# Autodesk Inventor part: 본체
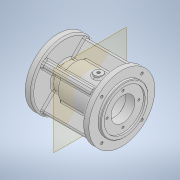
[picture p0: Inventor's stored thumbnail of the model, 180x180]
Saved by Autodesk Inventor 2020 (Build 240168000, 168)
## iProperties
Created: 2024-10
Part Number: 본체
Material: 일반
Document SubType Name: Modeling
Designer: oem
Density: 1 g/cm^3
Appearance: 기본값
Author: oem
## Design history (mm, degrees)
sketch "스케치1"
  geometry: L1 (-61, 0)-(61, 0); L2 (-61, 42)-(-56, 42); L3 (-56, 42)-(-56, 58); L4 (-56, 58)-(-44, 58); L5 (-44, 58)-(-44, 23); L6 (44, 58)-(56, 58); L7 (56, 58)-(56, 42); L8 (56, 42)-(61, 42); L9 (61, 42)-(61, 0); L10 (-61, 42)-(-61, 0); L11 (44, 58)-(44, 30); L12 (-44, 23)-(-29, 23); L13 (-29, 23)-(-29, 30); L14 (-29, 30)-(44, 30); 2 further points
  constraints: 28 end point, 7 perpendicular, 3 horizontal, 2 vertical, 1 coincident, 1 midpoint
  dimensions: "d0" = 122 distance of L1.start L1.end; "d1" = 5 distance of L2.start L2.end; "d3" = 116 diameter of L4 L1; "d4" = 84 diameter of L2 L1; "d5" = 116 diameter of L6 L1; "d6" = 84 diameter of L8 L1; "d7" = 5 distance of L7.end L8.end; "d8" = 12 distance of L6.start L6.end; "d9" = 15 distance of L5.end L12.end; "d10" = 46 diameter of L12 L1; "d11" = 60 diameter of L14 L1; "d12" = 12 distance of L3.end L4.end
revolve "회전1" sketch "스케치1" stored, may be unused: angle "d13" = 90 deg
sketch "스케치2"
  geometry: L1 (-41.012, 41.012)-(41.012, -41.012); L2 (41.012, 41.012)-(-41.012, -41.012); L3 (38.043, 38.043)-(21.213, 21.213); L4 (34.648, 41.719)-(12.339, 19.41); L5 (19.41, 12.339)-(41.719, 34.648); L6 (-38.043, 38.043)-(-21.213, 21.213); L7 (-41.719, 34.648)-(-19.41, 12.339); L8 (-12.339, 19.41)-(-34.648, 41.719); L9 (-41.719, 34.648)-(-34.648, 41.719); L10 (34.648, 41.719)-(41.719, 34.648); L11 (-58, 0)-(58, 0); C1 r 58 at (0, 0) reference; A1 r 30 centre (0, 0) between (21.213, 21.213) and (-21.213, 21.213) reference; A2 r 58 centre (0, 0) between (-41.012, 41.012) and (41.012, -41.012) reference; A3 r 23 centre (0, 0) between (12.339, 19.41) and (19.41, 12.339); 4 further points
  constraints: 26 end point, 12 point on circle, 4 point on line, 3 coincident, 3 midpoint, 2 parallel, 2 vertical alignment, 1 centre point, 1 horizontal
  dimensions: "d15" = 90 deg angle of L2 L1; "d18" = 54 distance from line of C1.centre L9; "d19" = 54 distance from line of L10 A1.centre; "d20" = 8.41512 horizontal distance of L6.end point (-29.628, 29.628); "d21" = 5 distance between parallel lines of L3 L4; "d22" = 5 distance between parallel lines of L8 L1; "d23" = 76.08689 distance of L3.start L6.start; "d24" = 10 distance of L7.start L8.end; "d25" = 10 distance of L4.start L5.end; "d28" = 46 diameter of A3; "d29" = 69.29646 distance of L4.start L8.end; "d30" = 83.4386 distance of L5.end L7.start
extrude "돌출1" join sketch "스케치2" stored distance "d26" = 10; taper "d27" = 0 deg
chamfer "모따기1" distance "d42" = 1; stored, may be unused: second distance "d43" = 2, angle "d44" = 45 deg
fillet "모깎기1" dims "d45" = 3
fillet "모깎기2" dims "d46" = 3
sketch "스케치5"
  geometry: C1 r 41 at (0, 0) reference; C2 r 36 at (0, 0)
  constraints: 1 centre point, 1 coincident
  dimensions: "d50" = 72 diameter of C2
extrude "돌출3" cut sketch "스케치5" distance "d51" = 3; taper "d52" = 0 deg
sketch "스케치6"
  geometry: C1 r 36 at (0, 0) reference; C2 r 21 at (0, 0)
  constraints: 1 centre point, 1 coincident
  dimensions: "d53" = 42 diameter of C2
extrude "돌출4" cut sketch "스케치6" distance "d54" = 16; taper "d55" = 0 deg
sketch "스케치7"
  geometry: C1 r 21 at (0, 0) reference; C2 r 25 at (0, 0)
  constraints: 1 centre point, 1 coincident
  dimensions: "d56" = 50 diameter of C2
extrude "돌출5" cut sketch "스케치7" distance "d57" = 54; taper "d58" = 0 deg
sketch "스케치9"
  geometry: C1 r 25 at (0, 0) reference; C2 r 21 at (0, 0)
  constraints: 1 centre point, 1 coincident
  dimensions: "d59" = 42 diameter of C2
extrude "돌출6" cut sketch "스케치9" distance "d60" = 12; taper "d61" = 0 deg
sketch "스케치10"
  geometry: C1 r 21 at (0, 0) reference; C2 r 18 at (0, 0)
  constraints: 1 centre point, 1 coincident
  dimensions: "d62" = 36 diameter of C2
extrude "돌출7" cut sketch "스케치10" distance "d63" = 18; taper "d64" = 0 deg
sketch "스케치11"
  geometry: C1 r 18 at (0, 0) reference; C2 r 16 at (0, 0)
  constraints: 1 centre point, 1 coincident
  dimensions: "d65" = 32 diameter of C2
extrude "돌출8" cut sketch "스케치11" distance "d66" = 4; taper "d67" = 0 deg
sketch "스케치12"
  geometry: C1 r 16 at (0, 0) reference; C2 r 10.5 at (0, 0)
  constraints: 1 centre point, 1 coincident
  dimensions: "d68" = 21 diameter of C2
extrude "돌출9" cut sketch "스케치12" distance "d69" = 3; taper "d70" = 0 deg
fillet "모깎기3" dims "d71" = 0.6
fillet "모깎기4" dims "d72" = 3
chamfer "모따기2" distance "d73" = 1; stored, may be unused: second distance "d74" = 2, angle "d75" = 45 deg
sketch "스케치13"
  geometry: C1 r 10.5 at (0, 0) reference; C2 r 36 at (0, 0)
  constraints: 1 centre point, 1 coincident
  dimensions: "d76" = 72 diameter of C2
extrude "돌출10" cut sketch "스케치13" distance "d77" = 4; taper "d78" = 0 deg
fillet "모깎기5" dims "d79" = 3
sketch "스케치14"
  geometry: C1 r 21 at (0, 0) reference; 1 further point
  constraints: 1 horizontal alignment
  dimensions: "d80" = 28 distance of point (28, 0) C1.centre
hole "구멍2" sketch "스케치14" at (28, 0) diameter "d81" = 4.134; stored, may be unused: countersink angle "d85" = 90 deg, drill point angle "d87" = 118 deg; dims "d82" = 10, "d83" = 11, "d84" = 6.6, "d86" = 12
sketch "스케치15"
  geometry: L1 (-35.355, 35.355)-(35.355, -35.355); L2 (35.355, 35.355)-(-35.355, -35.355); C1 r 42 at (0, 0) reference; A1 r 50 centre (0, 0) between (35.355, 35.355) and (35.355, -35.355)
  constraints: 4 end point, 4 point on circle, 2 horizontal alignment, 1 centre point, 1 coincident, 1 vertical alignment
  dimensions: "d91" = 100 diameter of A1; "d92" = 90 deg angle of L2 L1
hole "구멍3" sketch "스케치15" at (35.355, 35.355), (35.355, -35.355), (-35.355, 35.355), (-35.355, -35.355) diameter "d93" = 4.917; stored, may be unused: countersink angle "d97" = 90 deg, drill point angle "d99" = 118 deg; dims "d94" = 12, "d95" = 11, "d96" = 6.6, "d98" = 14
fillet "모깎기6" dims "d100" = 3
fillet "모깎기7" dims "d101" = 3
fillet "모깎기8" dims "d102" = 3
node "작업 평면2"
sketch "스케치16"
  geometry: L1 (-44, -43.412)-(-44, -55) reference; C1 r 7.5 at (-15, 0); 2 further points
  constraints: 1 centre point, 1 coincident, 1 horizontal alignment
  dimensions: "d104" = 29 distance from line of L1 point (-15, 0); "d105" = 15 diameter of C1
extrude "돌출11" join sketch "스케치16" stored distance "d106" = 4; taper "d107" = 0 deg
sketch "스케치17"
  geometry: C1 r 7.5 at (0, 0) reference; 1 further point
hole "구멍4" sketch "스케치17" at (0, 0) diameter "d108" = 5.1881; stored, may be unused: countersink angle "d112" = 90 deg, drill point angle "d114" = 118 deg; dims "d109" = 12, "d110" = 11, "d111" = 6.6, "d113" = 16
fillet "모깎기9" dims "d115" = 3
node "작업 평면4"
sketch "스케치19"
  geometry: L1 (61, 41)-(61, -41) reference; 2 further points
  constraints: 1 horizontal alignment, 1 other
  dimensions: "d118" = 52 distance from line of L1 point (9, 0)
feature "엠보싱1" sketch "스케치19" dims "d0" = 122, "d1" = 5, "d3" = 116, "d4" = 84, "d5" = 116, "d6" = 84, "d7" = 5, "d8" = 12, "d9" = 15, "d10" = 46, "d11" = 60, "d12" = 12, "d119" = 0.5, "d120" = 0
node "작업 평면5"
node "작업 평면6"
node "솔리드1"
mirror "미러1"
pattern_circular "원형 패턴2" dims angle "d89" = 360 deg
mirror "미러2"
mirror "미러4"
node "작업 평면1"
node "작업 평면3"
feature "A9D066F2-1C7D-4E18-AEED-F7BC21143FA4" dims "d81" = 4.134, "d82" = 10, "d83" = 11, "d84" = 6.6, "d85" = 90 deg, "d86" = 12, "d87" = 118 deg
other parameters: "d103" = -34
